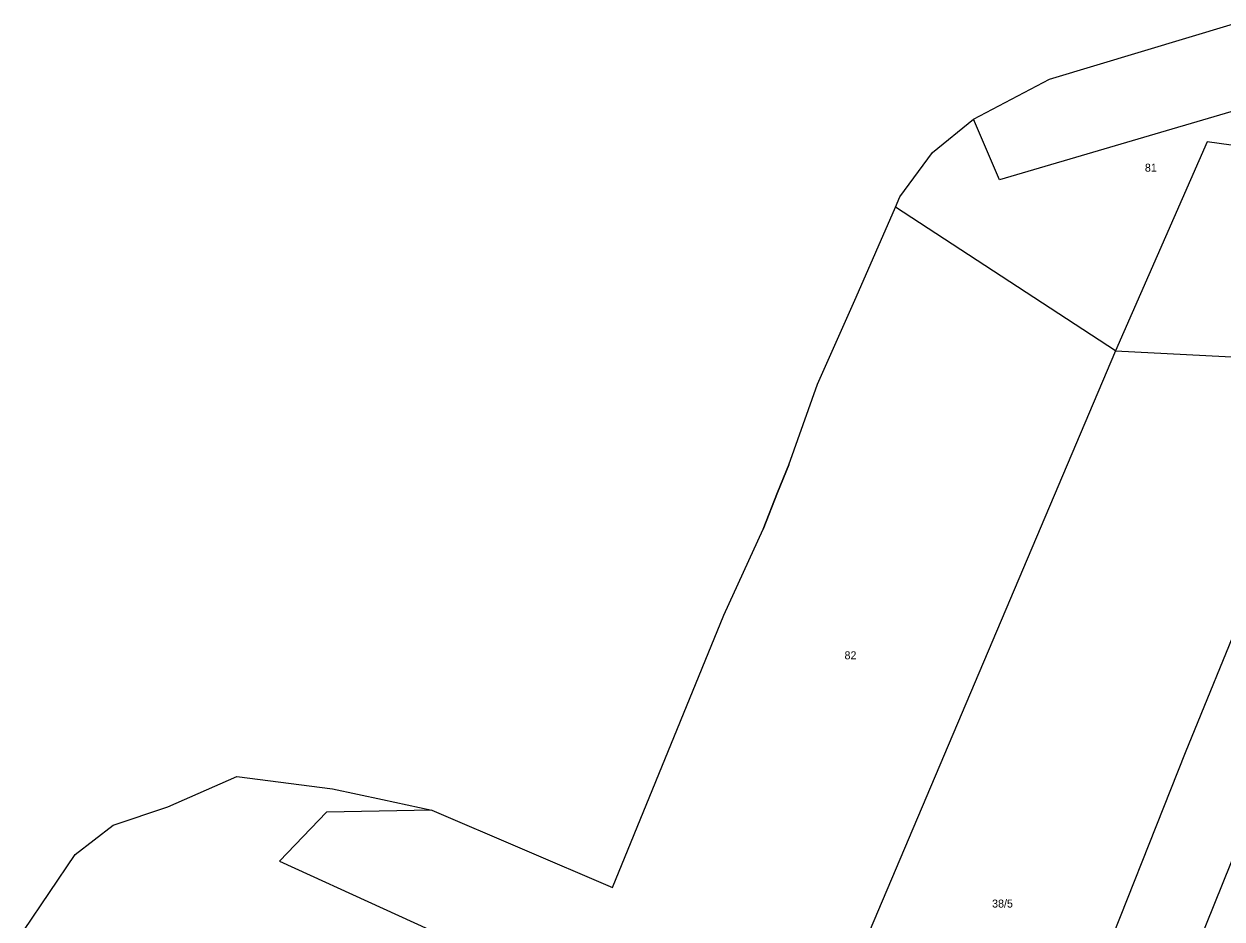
# Model space of a CAD drawing. Extents: x -747333 to -745433, y -1133152 to -1130600.
# Drawn here: x -746573.8 to -746319.4, y -1131144.2 to -1130953.9 of the extents above; entities that cross this region are included whole.
import ezdxf

# ---------------------------------------------------------------- set-up
doc = ezdxf.new("R2010")
doc.units = 0
for name, color, linetype in [('Vrstva 13', 7, 'Continuous'), ('Vrstva 18', 7, 'Continuous'), ('Vrstva 52', 7, 'Continuous'), ('Vrstva 6', 7, 'Continuous')]:
    doc.layers.add(name, color=color, linetype=linetype)

msp = doc.modelspace()

# ---------------------------------------------------------------- linework, layer by layer
at = {"layer": 'Vrstva 13'}
for points in [[(-746356.02, -1130965.68), (-746316.94, -1130953.92)], [(-746372.15, -1130974.18), (-746356.02, -1130965.68)], [(-746380.86, -1130981.26), (-746372.15, -1130974.18)], [(-746387.79, -1130990.68), (-746380.86, -1130981.26)], [(-746388.73, -1130992.84), (-746387.79, -1130990.68)], [(-746397.07, -1131012), (-746388.73, -1130992.84)], [(-746405.3, -1131030.48), (-746397.07, -1131012)], [(-746411.42, -1131047.62), (-746405.3, -1131030.48)], [(-746411.42, -1131047.62), (-746413.77, -1131053.53)], [(-746413.77, -1131053.53), (-746416.87, -1131061.3)], [(-746425.17, -1131079.57), (-746416.87, -1131061.3)], [(-746448.81, -1131137.42), (-746425.17, -1131079.57)], [(-746543.27, -1131120.29), (-746528.6, -1131113.84)], [(-746528.6, -1131113.84), (-746508.31, -1131116.49)], [(-746508.31, -1131116.49), (-746497.69, -1131118.76)], [(-746497.69, -1131118.76), (-746487.24, -1131121.05)], [(-746554.9, -1131124.21), (-746543.27, -1131120.29)], [(-746487.24, -1131121.05), (-746448.81, -1131137.42)], [(-746562.93, -1131130.47), (-746554.9, -1131124.21)], [(-746573.83, -1131146.6), (-746562.93, -1131130.47)]]:
    msp.add_lwpolyline(points, dxfattribs=at)
at = {"layer": 'Vrstva 52'}
msp.add_lwpolyline([(-746573.83, -1131146.6), (-746562.93, -1131130.47), (-746554.9, -1131124.21), (-746543.27, -1131120.29), (-746528.6, -1131113.84), (-746508.31, -1131116.49), (-746497.69, -1131118.76), (-746487.24, -1131121.05), (-746448.81, -1131137.42), (-746425.17, -1131079.57), (-746416.87, -1131061.3), (-746413.77, -1131053.53), (-746411.42, -1131047.62), (-746405.3, -1131030.48), (-746397.07, -1131012), (-746388.73, -1130992.84), (-746387.79, -1130990.68), (-746380.86, -1130981.26), (-746372.15, -1130974.18), (-746356.02, -1130965.68), (-746316.94, -1130953.92)], dxfattribs=at)
at = {"layer": 'Vrstva 6'}
for points in [[(-746262.36, -1130956.4), (-746366.62, -1130987.06)], [(-746366.62, -1130987.06), (-746372.15, -1130974.18)], [(-746322.52, -1130978.97), (-746342.01, -1131023.42)], [(-746274.22, -1130985.7), (-746322.52, -1130978.97)], [(-746342.01, -1131023.42), (-746388.73, -1130992.84)], [(-746342.01, -1131023.42), (-746394.35, -1131146.88)], [(-746342.01, -1131023.42), (-746292.67, -1131025.93)], [(-746314.54, -1131077.8), (-746327.19, -1131108.81)], [(-746327.19, -1131108.81), (-746347.24, -1131159.41)], [(-746509.57, -1131121.42), (-746519.56, -1131131.84)], [(-746487.24, -1131121.05), (-746509.57, -1131121.42)], [(-746335.21, -1131176.29), (-746315.62, -1131127.62)], [(-746519.56, -1131131.84), (-746409.45, -1131182.16)]]:
    msp.add_lwpolyline(points, dxfattribs=at)

# ---------------------------------------------------------------- texts
at = {"layer": 'Vrstva 18'}
for s, p in [('81', (-746335.77, -1130985.32)), ('82', (-746399.56, -1131088.96)), ('38/5', (-746368.22, -1131141.72))]:
    msp.add_text(s, height=1.7, dxfattribs=at).set_placement(p)

doc.saveas('drawing.dxf')
